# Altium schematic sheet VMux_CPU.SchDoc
size A4; DocumentNumber: 2; SheetNumber: 2; SheetTotal: 5
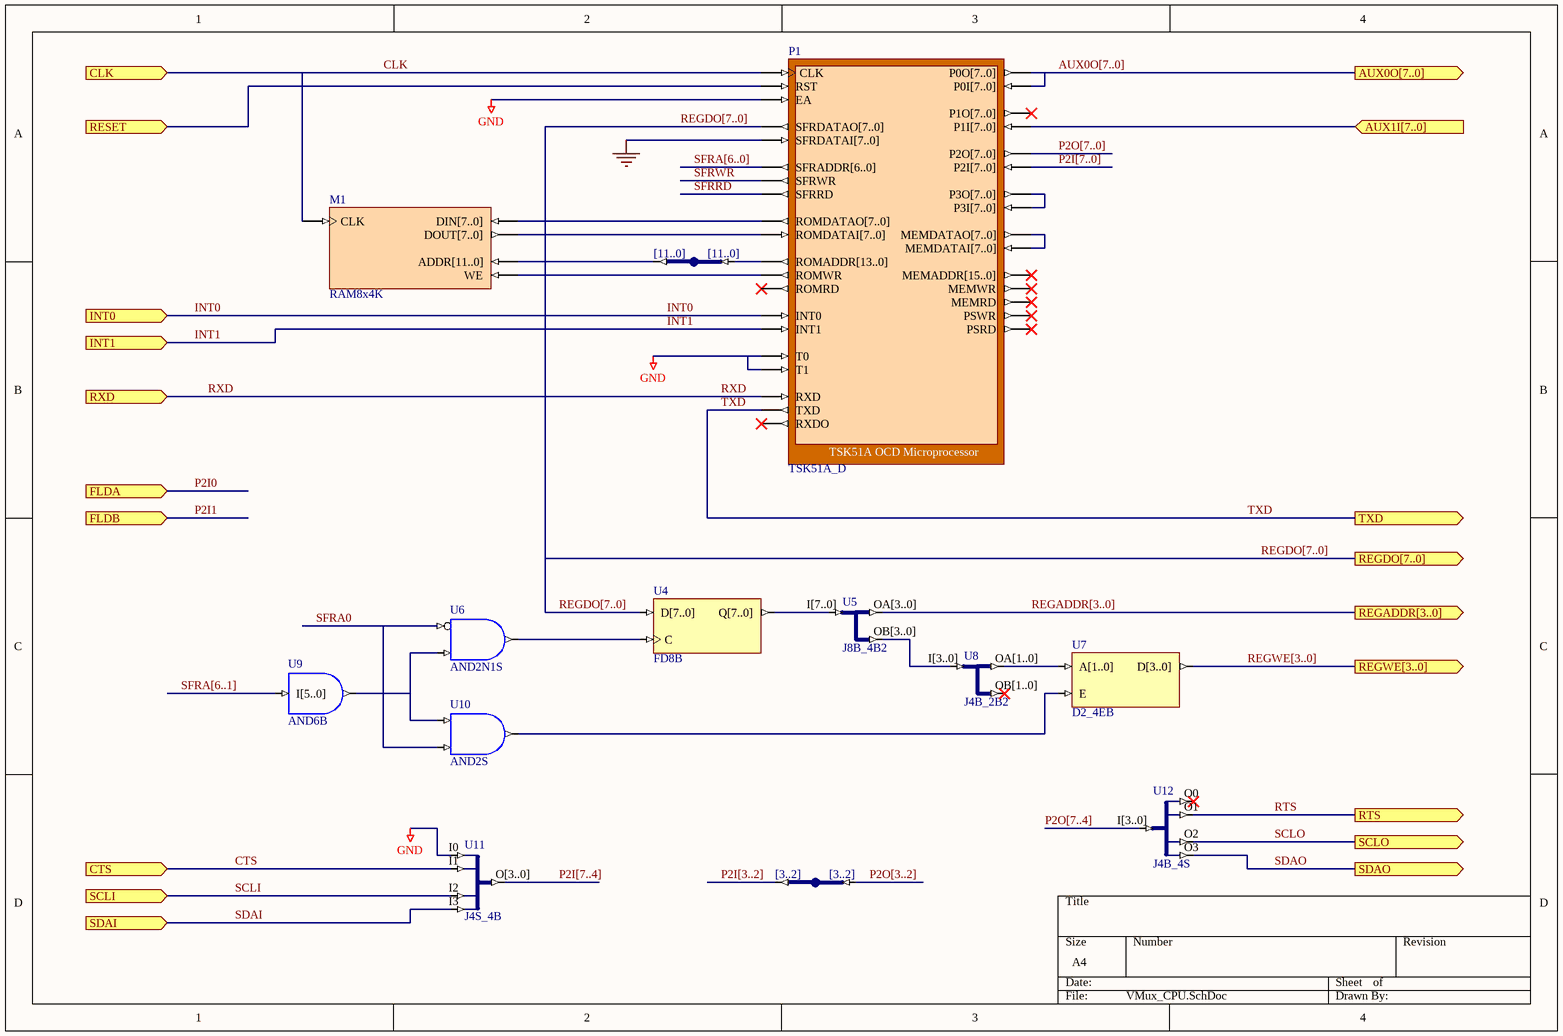
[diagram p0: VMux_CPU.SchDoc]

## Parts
M1  RAM8x4K
P1  TSK51A_D
U2  IndexA: [11..0]  (hidden comment: JB)
U3  IndexA: [3..2]  (hidden comment: JB)
U4  FD8B
U5  J8B_4B2
U6  AND2N1S
U7  D2_4EB
U8  J4B_2B2
U9  AND6B
U10  AND2S
U11  J4S_4B
U12  J4B_4S

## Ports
AUX0O[7..0] (out), AUX1I[7..0] (in), CLK (in), CTS (in), FLDA (in), FLDB (in), INT0 (in), INT1 (in), REGADDR[3..0] (out), REGDO[7..0] (out), REGWE[3..0] (out), RESET (in), RTS (out), RXD (in), SCLI (in), SCLO (out), SDAI (in), SDAO (out), TXD (out)

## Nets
GND: P1.EA P1.T0 P1.T1 U11.I0
CLK: M1.CLK P1.CLK ; port CLK
CTS: U11.I1 ; port CTS
INT0: P1.INT0 ; port INT0
INT1: P1.INT1 ; port INT1
RESET: P1.RST ; port RESET
RTS: U12.O1 ; port RTS
RXD: P1.RXD ; port RXD
SCLI: U11.I2 ; port SCLI
SCLO: U12.O2 ; port SCLO
SDAI: U11.I3 ; port SDAI
SDAO: U12.O3 ; port SDAO
SFRA0: U6.I0 U10.I1
SFRRD: P1.SFRRD
SFRWR: P1.SFRWR
TXD: P1.TXD ; port TXD
NetM1_WE: M1.WE P1.ROMWR
NetU4_C: U4.C U6.O
NetU6_I1: U6.I1 U9.O U10.I0
NetU7_E: U7.E U10.O

Not connected (* = marked no-connect by the designer): M1 ADDR[11..0] DIN[7..0] DOUT[7..0]; P1 MEMADDR[15..0]* MEMDATAI[7..0] MEMDATAO[7..0] MEMRD* MEMWR* P0I[7..0] P0O[7..0] P1I[7..0] P1O[7..0]* P2I[7..0] P2O[7..0] P3I[7..0] P3O[7..0] PSRD* PSWR* ROMADDR[13..0] ROMDATAI[7..0] ROMDATAO[7..0] ROMRD* RXDO* SFRADDR[6..0] SFRDATAI[7..0] SFRDATAO[7..0]; U2 A[0..0](IA[0..0]) B[0..0]; U3 A[0..0](IA[0..0]) B[0..0]; U4 D[7..0] Q[7..0]; U5 I[7..0] OA[3..0] OB[3..0]; U7 A[1..0] D[3..0]; U8 I[3..0] OA[1..0] OB[1..0]*; U9 I[5..0]; U11 O[3..0]; U12 I[3..0] O0*

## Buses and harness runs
bus AUX0O[7..0] = port AUX0O[7..0]
bus P2I[3..2]
bus P2I[7..0]
bus P2I[7..4]
bus P2O[3..2]
bus P2O[7..0]
bus P2O[7..4]
bus REGADDR[3..0] = port REGADDR[3..0]
bus REGDO[7..0] = port REGDO[7..0]
bus REGWE[3..0] = port REGWE[3..0]
bus SFRA[6..0]
bus SFRA[6..1]

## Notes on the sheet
- Labels drawn without touching a wire or pin: GNDBUS[..]

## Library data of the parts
M1 = RAM8x4K: Single Port Random Access Memory 4096 x 8; Memory_Depth: 4096; Memory_Type: RAM_SinglePortBlock; Memory_Width: 8; Memory_ClockEdge: Rising; Nexus_Core: Memory_Program
P1 = TSK51A_D: TSK51A OCD Microprocessor; NEXUS_CORE: Processor_OCDS; NEXUS_JTAG_DEVICE: True; NEXUS_JTAG_ORDER: 0; ChildModel1: RAM256x8_TSK51D; ChildCore1: M1; Memory_Configuration: Record[NEXUS_CORE]{}ComponentDesignator[iram]{}Memory_Depth[256]{}Memory_UsageType[ram]{}ProgramDownloadAddress[0x0]{}Memory_BusType[c51:idata_bus]{n}Record[NEXUS_CORE]{}ComponentDesignator[xram]{}Memory_Depth[64k]{}Memory_UsageType[ram]{}ProgramDownloadAddress[0x0]{}Memory_BusType[c51:xdata_bus]{n}Record[NEXUS_CORE]{}ComponentDesignator[xrom]{}Memory_Depth[64k]{}Memory_UsageType[rom]{}ProgramDownloadAddress[0x0]{}Memory_BusType[c51:code_bus]{n}
U2 U3 = JB: System Joiner; Class I: Bus Joiner; ArchiveName: GENERIC
U4 = FD8B: 8-Bit D-Type Flip-Flop, Bus Version; Xilinx Equivalent: FD8; ArchiveName: GENERIC
U5 = J8B_4B2: 1 x 8-bit input bus to 2 x 4-Bit output bus; ArchiveName: GENERIC
U6 = AND2N1S: 2-Input AND Gate with Active Low A Input, Single Pin Version; Xilinx Equivalent: AND2B1; ArchiveName: GENERIC
U7 = D2_4EB: Binary 2- to 4-Bit Decoder with Enable, Bus Version; ArchiveName: GENERIC
U8 = J4B_2B2: 1 x 4-bit input bus to 2 x 2-Bit output bus; ArchiveName: GENERIC
U9 = AND6B: 6-Input AND Gate, Bus Version; ArchiveName: GENERIC
U10 = AND2S: 2-Input AND Gate, Single Pin Version; Xilinx Equivalent: AND2; ArchiveName: GENERIC
U11 = J4S_4B: 4 Single pin inputs to single 4-Bit output bus; ArchiveName: GENERIC
U12 = J4B_4S: 4-Bit input bus to 4 Single pin outputs; ArchiveName: GENERIC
